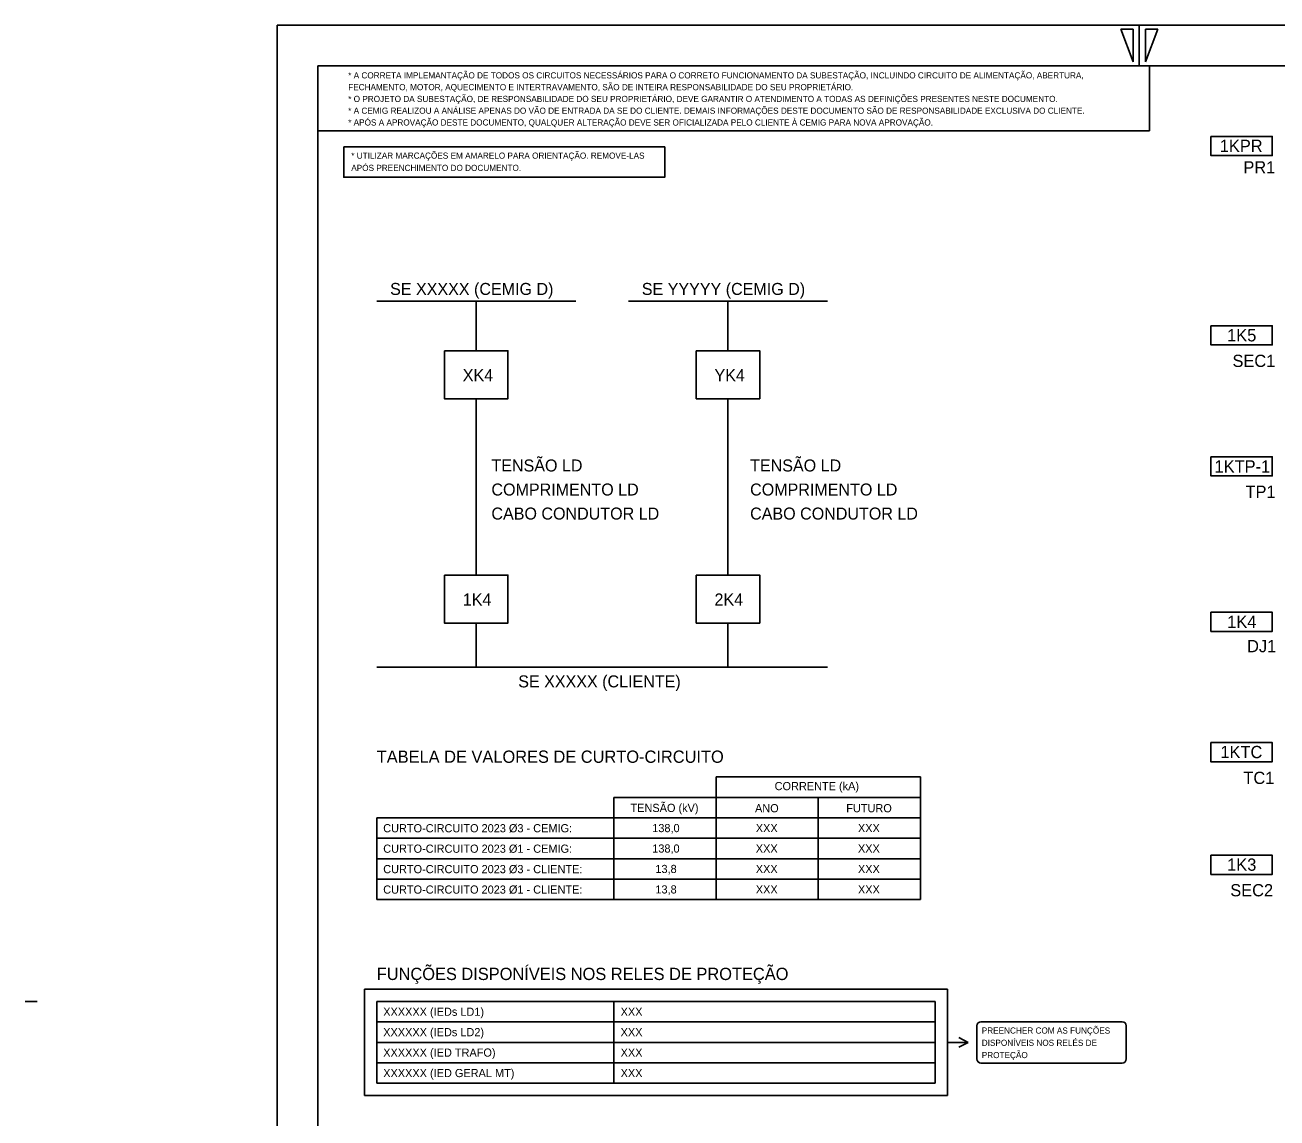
# Model space of a CAD drawing. Extents: x 501 to 1404, y 358 to 952.
# Drawn here: x 500.9 to 807.3, y 684.6 to 952 of the extents above; entities that cross this region are included whole.
import ezdxf

# ---------------------------------------------------------------- set-up
doc = ezdxf.new("R2010")
doc.units = 0
doc.layers.add('New Level (0)', color=7, linetype='Continuous')

# ---------------------------------------------------------------- blocks, each defined once
blk = doc.blocks.new('POINT_DISPLAY')
blk.add_line((0, 0), (0, 0))

msp = doc.modelspace()

# ---------------------------------------------------------------- linework, layer by layer
for p, q in [((586.96, 884.4), (635.66, 884.4)), ((611.31, 884.4), (611.31, 872.28)), ((648.56, 884.4), (697.25, 884.4)), ((672.91, 884.4), (672.91, 872.28)), ((611.31, 860.54), (611.31, 817.4)), ((672.91, 860.54), (672.91, 817.4)), ((611.31, 805.67), (611.31, 794.9)), ((672.91, 805.67), (672.91, 794.9)), ((586.96, 794.9), (697.25, 794.9))]:
    msp.add_line(p, q)
for points in [[(603.54, 872.28), (619.08, 872.28), (619.08, 860.54), (603.54, 860.54)], [(665.14, 872.28), (680.68, 872.28), (680.68, 860.54), (665.14, 860.54)], [(603.54, 817.4), (619.08, 817.4), (619.08, 805.67), (603.54, 805.67)], [(665.14, 817.4), (680.68, 817.4), (680.68, 805.67), (665.14, 805.67)]]:
    msp.add_lwpolyline(points, close=True)
at = {"layer": 'New Level (0)'}
for p, q in [((562.58, 951.96), (562.58, 357.96)), ((1403.58, 951.96), (562.58, 951.96)), ((1403.58, 951.96), (562.58, 951.96)), ((562.58, 951.96), (562.58, 357.96)), ((772.08, 950.96), (769.08, 950.96)), ((769.08, 950.96), (772.08, 942.96)), ((772.08, 942.96), (772.08, 950.96)), ((773.58, 951.96), (773.58, 941.96)), ((775.08, 942.96), (775.08, 950.96)), ((775.08, 950.96), (778.08, 950.96)), ((778.08, 950.96), (775.08, 942.96)), ((572.58, 941.96), (572.58, 367.96)), ((1393.58, 941.96), (572.58, 941.96)), ((572.58, 941.96), (572.58, 367.96)), ((670.01, 768.04), (670.01, 738.04)), ((670.01, 768.04), (720.01, 768.04)), ((720.01, 768.04), (720.01, 738.04)), ((645.01, 763.04), (645.01, 738.04)), ((645.01, 763.04), (720.01, 763.04)), ((695.01, 763.04), (695.01, 738.04)), ((586.96, 758.04), (720.01, 758.04)), ((586.96, 758.04), (586.96, 738.04)), ((586.96, 753.04), (720.01, 753.04)), ((586.96, 748.04), (720.01, 748.04)), ((586.96, 743.04), (720.01, 743.04)), ((586.96, 738.04), (720.01, 738.04)), ((583.96, 716.12), (726.65, 716.12)), ((583.96, 716.12), (583.96, 690.12)), ((726.65, 716.12), (726.65, 690.12)), ((500.89, 713.12), (503.89, 713.12)), ((586.96, 713.12), (723.65, 713.12)), ((586.96, 713.12), (586.96, 693.12)), ((645.01, 713.12), (645.01, 693.12)), ((723.65, 713.12), (723.65, 693.12)), ((586.96, 708.12), (723.65, 708.12)), ((734.84, 708.17), (742.19, 708.17)), ((742.19, 708.17), (769.38, 708.17)), ((733.84, 699.06), (733.84, 707.17)), ((770.38, 707.17), (770.38, 699.06)), ((586.96, 703.12), (723.65, 703.12)), ((726.65, 703.12), (731.68, 703.12)), ((731.68, 703.12), (729.38, 704.33)), ((731.68, 703.12), (729.38, 701.91)), ((586.96, 698.12), (723.65, 698.12)), ((769.38, 698.06), (734.84, 698.06)), ((586.96, 693.12), (723.65, 693.12)), ((726.65, 690.12), (583.96, 690.12))]:
    msp.add_line(p, q, dxfattribs=at)
for points in [[(572.58, 941.96), (776.08, 941.96), (776.08, 926.09), (572.58, 926.09)], [(791.1, 924.73), (806.12, 924.73), (806.12, 920.04), (791.1, 920.04)], [(578.87, 922.15), (657.43, 922.15), (657.43, 914.73), (578.87, 914.73)], [(791.1, 878.4), (806.12, 878.4), (806.12, 873.72), (791.1, 873.72)], [(791.1, 846.35), (806.12, 846.35), (806.12, 841.67), (791.1, 841.67)], [(791.1, 808.32), (806.12, 808.32), (806.12, 803.64), (791.1, 803.64)], [(791.09, 776.46), (806.11, 776.46), (806.11, 771.77), (791.09, 771.77)], [(791.1, 748.9), (806.12, 748.9), (806.12, 744.22), (791.1, 744.22)]]:
    msp.add_lwpolyline(points, close=True, dxfattribs=at)
for centre, start, end in [((734.84, 707.17), 90, 180), ((769.38, 707.17), 0, 90), ((734.84, 699.06), 180, 270), ((769.38, 699.06), 270, 0)]:
    msp.add_arc(centre, 1, start, end, dxfattribs=at)

# ---------------------------------------------------------------- block references
for p in [(670.01, 758.04), (670.01, 713.12)]:
    msp.add_blockref('POINT_DISPLAY', p, dxfattribs=at)

# ---------------------------------------------------------------- texts
for s, height, p in [('1KPR', 3, (793.28, 920.91)), ('* UTILIZAR MARCAÇÕES EM AMARELO PARA ORIENTAÇÃO. REMOVE-LAS ', 1.5, (580.73, 919.27)), ('APÓS PREENCHIMENTO DO DOCUMENTO.', 1.5, (580.73, 916.27)), ('PR1', 3, (799.06, 915.66)), ('SE XXXXX (CEMIG D)', 2.94, (590.23, 885.94)), ('SE YYYYY (CEMIG D)', 2.94, (651.83, 885.94)), ('1K5', 3, (795.08, 874.58)), ('SEC1', 3, (796.39, 868.32)), ('XK4', 2.94, (608.02, 864.85)), ('YK4', 2.94, (669.62, 864.85)), ('TENSÃO LD ', 2.94, (615.03, 842.76)), ('TENSÃO LD ', 2.94, (678.34, 842.76)), ('1KTP-1', 3, (792, 842.5)), ('COMPRIMENTO LD', 2.94, (615.03, 836.88)), ('COMPRIMENTO LD', 2.94, (678.34, 836.88)), ('TP1', 3, (799.57, 836.31)), ('CABO CONDUTOR LD ', 2.94, (615.03, 831)), ('CABO CONDUTOR LD ', 2.94, (678.34, 831)), ('1K4', 2.94, (608.02, 809.98)), ('2K4', 2.94, (669.62, 809.98)), ('1K4', 3, (795.1, 804.5)), ('DJ1', 3, (799.97, 798.55)), ('SE XXXXX (CLIENTE)', 2.94, (621.59, 789.95)), ('1KTC', 3, (793.44, 772.64)), ('TABELA DE VALORES DE CURTO-CIRCUITO', 3, (586.96, 771.5)), ('TC1', 3, (799.06, 766.32)), ('CORRENTE (kA)', 2, (684.34, 764.81)), ('TENSÃO (kV)', 2, (649.07, 759.48)), ('ANO', 2, (679.54, 759.4)), ('FUTURO', 2, (701.87, 759.4)), ('CURTO-CIRCUITO 2023 Ø3 - CEMIG:', 2, (588.55, 754.5)), ('138,0', 2, (654.39, 754.54)), ('XXX', 2, (679.73, 754.54)), ('XXX', 2, (704.73, 754.54)), ('CURTO-CIRCUITO 2023 Ø1 - CEMIG:', 2, (588.55, 749.5)), ('138,0', 2, (654.39, 749.54)), ('XXX', 2, (679.73, 749.54)), ('XXX', 2, (704.73, 749.54)), ('1K3', 3, (795.09, 745.1)), ('CURTO-CIRCUITO 2023 Ø3 - CLIENTE:', 2, (588.55, 744.5)), ('13,8', 2, (655.16, 744.54)), ('XXX', 2, (679.73, 744.54)), ('XXX', 2, (704.73, 744.54)), ('CURTO-CIRCUITO 2023 Ø1 - CLIENTE:', 2, (588.55, 739.5)), ('13,8', 2, (655.16, 739.54)), ('XXX', 2, (679.73, 739.54)), ('XXX', 2, (704.73, 739.54)), ('SEC2', 3, (795.85, 738.84)), ('FUNÇÕES DISPONÍVEIS NOS RELES DE PROTEÇÃO', 3, (586.96, 718.37)), ('XXXXXX (IEDs LD1)', 2, (588.55, 709.62)), ('XXX', 2, (646.65, 709.62)), ('XXXXXX (IEDs LD2)', 2, (588.55, 704.62)), ('XXX', 2, (646.65, 704.62)), ('PREENCHER COM AS FUNÇÕES ', 1.5, (735.03, 705.27)), ('XXXXXX (IED TRAFO)', 2, (588.55, 699.62)), ('DISPONÍVEIS NOS RELÉS DE ', 1.5, (735.03, 702.27)), ('XXX', 2, (646.65, 699.62)), ('PROTEÇÃO', 1.5, (735.03, 699.27)), ('XXXXXX (IED GERAL MT)', 2, (588.55, 694.62)), ('XXX', 2, (646.65, 694.62))]:
    msp.add_text(s, height=height).set_placement(p)
for s, p in [('* A CORRETA IMPLEMANTAÇÃO DE TODOS OS CIRCUITOS NECESSÁRIOS PARA O CORRETO FUNCIONAMENTO DA SUBESTAÇÃO, INCLUINDO CIRCUITO DE ALIMENTAÇÃO, ABERTURA,   ', (579.98, 938.9)), ('FECHAMENTO, MOTOR, AQUECIMENTO E INTERTRAVAMENTO, SÃO DE INTEIRA RESPONSABILIDADE DO SEU PROPRIETÁRIO.', (579.98, 936.02)), ('* O PROJETO DA SUBESTAÇÃO, DE RESPONSABILIDADE DO SEU PROPRIETÁRIO, DEVE GARANTIR O ATENDIMENTO A TODAS AS DEFINIÇÕES PRESENTES NESTE DOCUMENTO.', (579.98, 933.14)), ('* A CEMIG REALIZOU A ANÁLISE APENAS DO VÃO DE ENTRADA DA SE DO CLIENTE. DEMAIS INFORMAÇÕES DESTE DOCUMENTO SÃO DE RESPONSABILIDADE EXCLUSIVA DO CLIENTE.', (579.98, 930.26)), ('* APÓS A APROVAÇÃO DESTE DOCUMENTO, QUALQUER ALTERAÇÃO DEVE SER OFICIALIZADA PELO CLIENTE À CEMIG PARA NOVA APROVAÇÃO.', (579.98, 927.38))]:
    msp.add_text(s, height=1.5, dxfattribs=at).set_placement(p)

doc.saveas('drawing.dxf')
